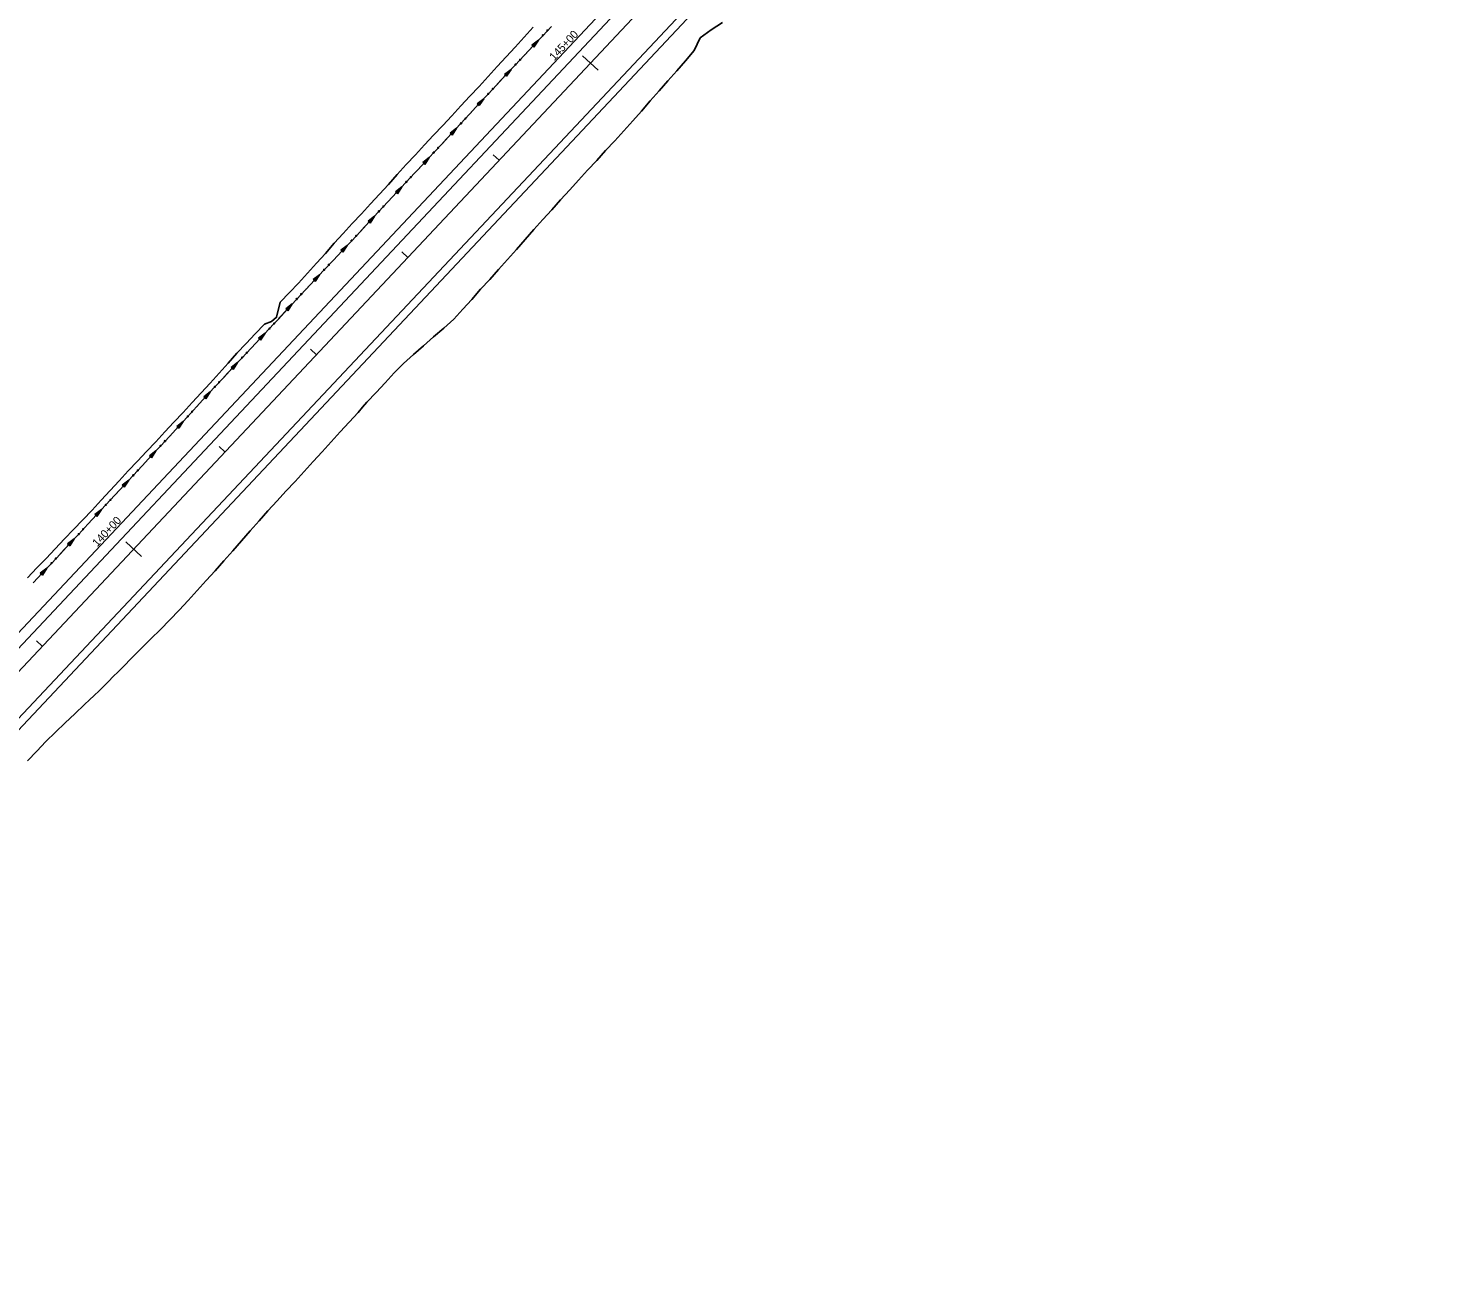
# Model space of a CAD drawing. Extents: x 1375694 to 1433473, y 1931050 to 1967991.
# Drawn here: x 1378305 to 1379358, y 1933391 to 1934333 of the extents above; entities that cross this region are included whole.
import ezdxf

# ---------------------------------------------------------------- set-up
doc = ezdxf.new("R2010")
doc.units = 0
for name, color, linetype in [('62', 7, 'Continuous'), ('R_Horz Alg', 7, 'Continuous'), ('R_Horz Alg Annot', 7, 'Continuous'), ('R_Proposed Const Limits', 7, 'Continuous'), ('R_Proposed Road', 7, 'Continuous')]:
    doc.layers.add(name, color=color, linetype=linetype)

msp = doc.modelspace()

# ---------------------------------------------------------------- linework, layer by layer
at = {"layer": '62'}
for p, q in [((1378687.5, 1934324.3), (1378682.7, 1934320.6)), ((1378682.7, 1934320.6), (1378684.2, 1934319.2)), ((1378684.2, 1934319.2), (1378687.5, 1934324.3)), ((1378667, 1934302.4), (1378662.1, 1934298.7)), ((1378662.1, 1934298.7), (1378663.7, 1934297.3)), ((1378663.7, 1934297.3), (1378667, 1934302.4)), ((1378646.5, 1934280.4), (1378641.7, 1934276.7)), ((1378641.7, 1934276.7), (1378643.2, 1934275.3)), ((1378643.2, 1934275.3), (1378646.5, 1934280.4)), ((1378626.1, 1934258.3), (1378621.3, 1934254.7)), ((1378621.3, 1934254.7), (1378622.8, 1934253.2)), ((1378622.8, 1934253.2), (1378626.1, 1934258.3)), ((1378605.6, 1934236.4), (1378600.8, 1934232.7)), ((1378600.8, 1934232.7), (1378602.3, 1934231.3)), ((1378602.3, 1934231.3), (1378605.6, 1934236.4)), ((1378585.1, 1934214.4), (1378580.3, 1934210.8)), ((1378580.3, 1934210.8), (1378581.8, 1934209.3)), ((1378581.8, 1934209.3), (1378585.1, 1934214.4)), ((1378564.6, 1934192.5), (1378559.8, 1934188.8)), ((1378561.3, 1934187.3), (1378564.6, 1934192.5)), ((1378559.8, 1934188.8), (1378561.3, 1934187.3)), ((1378544.1, 1934170.5), (1378539.3, 1934166.9)), ((1378540.8, 1934165.4), (1378544.1, 1934170.5)), ((1378539.3, 1934166.9), (1378540.8, 1934165.4)), ((1378523.5, 1934148.6), (1378518.7, 1934145)), ((1378520.2, 1934143.5), (1378523.5, 1934148.6)), ((1378518.7, 1934145), (1378520.2, 1934143.5)), ((1378503, 1934126.7), (1378498.2, 1934123)), ((1378499.7, 1934121.6), (1378503, 1934126.7)), ((1378498.2, 1934123), (1378499.7, 1934121.6)), ((1378482.6, 1934104.7), (1378477.7, 1934101)), ((1378477.7, 1934101), (1378479.3, 1934099.6)), ((1378479.3, 1934099.6), (1378482.6, 1934104.7)), ((1378462, 1934082.8), (1378457.1, 1934079.1)), ((1378457.1, 1934079.1), (1378458.7, 1934077.7)), ((1378458.7, 1934077.7), (1378462, 1934082.8)), ((1378441.5, 1934060.8), (1378436.7, 1934057.1)), ((1378436.7, 1934057.1), (1378438.3, 1934055.7)), ((1378438.3, 1934055.7), (1378441.5, 1934060.8)), ((1378421.2, 1934038.7), (1378416.4, 1934035)), ((1378416.4, 1934035), (1378417.9, 1934033.6)), ((1378417.9, 1934033.6), (1378421.2, 1934038.7)), ((1378400.8, 1934016.6), (1378396, 1934013)), ((1378396, 1934013), (1378397.5, 1934011.5)), ((1378397.5, 1934011.5), (1378400.8, 1934016.6)), ((1378380.4, 1933994.6), (1378375.6, 1933990.9)), ((1378375.6, 1933990.9), (1378377.1, 1933989.5)), ((1378377.1, 1933989.5), (1378380.4, 1933994.6)), ((1378360, 1933972.6), (1378355.1, 1933968.9)), ((1378355.1, 1933968.9), (1378356.6, 1933967.5)), ((1378356.6, 1933967.5), (1378360, 1933972.6)), ((1378339.5, 1933950.6), (1378334.6, 1933947)), ((1378334.6, 1933947), (1378336.2, 1933945.5)), ((1378336.2, 1933945.5), (1378339.5, 1933950.6)), ((1378319, 1933928.7), (1378314.1, 1933925)), ((1378315.7, 1933923.6), (1378319, 1933928.7)), ((1378314.1, 1933925), (1378315.7, 1933923.6))]:
    msp.add_line(p, q, dxfattribs=at)
for points in [[(1378308.8, 1933917.7), (1378315.6, 1933925), (1378322.4, 1933932.3), (1378329.2, 1933939.6), (1378336, 1933946.9), (1378342.9, 1933954.3), (1378349.7, 1933961.6), (1378356.5, 1933968.9), (1378363.3, 1933976.2), (1378370.1, 1933983.5), (1378376.9, 1933990.9), (1378383.7, 1933998.2), (1378390.5, 1934005.5), (1378397.3, 1934012.9), (1378404.1, 1934020.2), (1378410.9, 1934027.5), (1378417.7, 1934034.9), (1378424.5, 1934042.2), (1378431.2, 1934049.6), (1378438, 1934057), (1378444.8, 1934064.3), (1378451.6, 1934071.7), (1378458.4, 1934079), (1378465.3, 1934086.2), (1378472.1, 1934093.5), (1378479, 1934100.8), (1378485.8, 1934108.1), (1378489.2, 1934111.8), (1378492.6, 1934115.4), (1378499.4, 1934122.8), (1378506.2, 1934130.1), (1378513, 1934137.4), (1378519.9, 1934144.7), (1378526.7, 1934152), (1378533.6, 1934159.3), (1378540.4, 1934166.6), (1378547.3, 1934173.8), (1378554.1, 1934181.1), (1378560.9, 1934188.5), (1378567.7, 1934195.8), (1378574.6, 1934203.1), (1378581.4, 1934210.4), (1378588.2, 1934217.7), (1378595, 1934225), (1378601.9, 1934232.3), (1378608.7, 1934239.6), (1378615.5, 1934246.9), (1378622.3, 1934254.3), (1378629.1, 1934261.6), (1378635.9, 1934268.9), (1378642.7, 1934276.3), (1378649.5, 1934283.6), (1378656.3, 1934291), (1378663.1, 1934298.3), (1378670, 1934305.6), (1378676.8, 1934312.9), (1378683.6, 1934320.1), (1378690.5, 1934327.4), (1378697.3, 1934334.7)], [(1378677.3, 1934313.3), (1378683.6, 1934320.1), (1378687.5, 1934324.3)], [(1378677.2, 1934313.3), (1378677.3, 1934313.3)], [(1378656.7, 1934291.4), (1378663.1, 1934298.3), (1378667, 1934302.4)], [(1378656.7, 1934291.4), (1378656.7, 1934291.4)], [(1378636.3, 1934269.4), (1378642.7, 1934276.3), (1378646.5, 1934280.4)], [(1378636.3, 1934269.4), (1378636.3, 1934269.4)], [(1378615.9, 1934247.4), (1378622.3, 1934254.3), (1378626.1, 1934258.3)], [(1378615.9, 1934247.3), (1378615.9, 1934247.4)], [(1378595.4, 1934225.4), (1378601.9, 1934232.3), (1378605.6, 1934236.4)], [(1378595.4, 1934225.4), (1378595.4, 1934225.4)], [(1378574.9, 1934203.5), (1378581.4, 1934210.4), (1378585.1, 1934214.4)], [(1378574.9, 1934203.4), (1378574.9, 1934203.5)], [(1378554.4, 1934181.5), (1378560.9, 1934188.5), (1378564.6, 1934192.5)], [(1378554.4, 1934181.4), (1378554.4, 1934181.5)], [(1378533.9, 1934159.6), (1378540.4, 1934166.6), (1378544.1, 1934170.5)], [(1378533.8, 1934159.6), (1378533.9, 1934159.6)], [(1378513.3, 1934137.7), (1378519.9, 1934144.7), (1378523.5, 1934148.6)], [(1378513.2, 1934137.7), (1378513.3, 1934137.7)], [(1378492.8, 1934115.7), (1378499.4, 1934122.8), (1378503, 1934126.7)], [(1378492.8, 1934115.7), (1378492.8, 1934115.7)], [(1378472.3, 1934093.7), (1378479, 1934100.8), (1378482.6, 1934104.7)], [(1378472.3, 1934093.7), (1378472.3, 1934093.7)], [(1378451.7, 1934071.9), (1378458.4, 1934079), (1378462, 1934082.8)], [(1378451.7, 1934071.8), (1378451.7, 1934071.9)], [(1378431.4, 1934049.8), (1378438, 1934057), (1378441.5, 1934060.8)], [(1378431.4, 1934049.7), (1378431.4, 1934049.8)], [(1378411.1, 1934027.7), (1378417.7, 1934034.9), (1378421.2, 1934038.7)], [(1378411, 1934027.6), (1378411.1, 1934027.7)], [(1378390.6, 1934005.6), (1378397.3, 1934012.9), (1378400.8, 1934016.6)], [(1378390.6, 1934005.6), (1378390.6, 1934005.6)], [(1378370.2, 1933983.6), (1378376.9, 1933990.9), (1378380.4, 1933994.6)], [(1378370.2, 1933983.6), (1378370.2, 1933983.6)], [(1378349.7, 1933961.6), (1378356.5, 1933968.9), (1378360, 1933972.6)], [(1378349.7, 1933961.6), (1378349.7, 1933961.6)], [(1378329.3, 1933939.7), (1378336, 1933946.9), (1378339.5, 1933950.6)], [(1378329.2, 1933939.6), (1378329.2, 1933939.6), (1378329.3, 1933939.7)], [(1378308.8, 1933917.7), (1378315.6, 1933925), (1378319, 1933928.7)]]:
    msp.add_lwpolyline(points, dxfattribs=at)
for centre in [(1378690.9, 1934328), (1378694.3, 1934331.6), (1378670.4, 1934306.1), (1378673.8, 1934309.7), (1378649.9, 1934284.1), (1378653.3, 1934287.8), (1378632.9, 1934265.7), (1378629.5, 1934262), (1378612.4, 1934243.7), (1378609, 1934240.1), (1378591.9, 1934221.8), (1378588.5, 1934218.1), (1378571.4, 1934199.8), (1378568, 1934196.1), (1378547.5, 1934174.2), (1378551, 1934177.8), (1378526.9, 1934152.3), (1378530.4, 1934156), (1378506.4, 1934130.4), (1378509.8, 1934134.1), (1378486, 1934108.3), (1378489.4, 1934112), (1378465.4, 1934086.5), (1378468.9, 1934090.1), (1378444.9, 1934064.5), (1378448.3, 1934068.2), (1378424.6, 1934042.4), (1378428, 1934046.1), (1378404.2, 1934020.3), (1378407.6, 1934024), (1378387.2, 1934002), (1378383.8, 1933998.3), (1378366.8, 1933980), (1378363.3, 1933976.3), (1378346.3, 1933958), (1378342.9, 1933954.3), (1378325.8, 1933936), (1378322.4, 1933932.4)]:
    msp.add_circle(centre, 0.375, dxfattribs=at)
at = {"layer": 'R_Horz Alg'}
msp.add_line((1377884.3, 1933411.6), (1379607.9, 1935244.4), dxfattribs=at)
at = {"layer": 'R_Horz Alg Annot'}
for points in [[(1378720.7, 1934312.7), (1378732.4, 1934301.8)], [(1378653.7, 1934238.5), (1378658.1, 1934234.4)], [(1378585.2, 1934165.7), (1378589.6, 1934161.5)], [(1378516.7, 1934092.8), (1378521.1, 1934088.7)], [(1378448.2, 1934020), (1378452.5, 1934015.8)], [(1378378.2, 1933948.5), (1378389.9, 1933937.5)], [(1378311.2, 1933874.3), (1378315.5, 1933870.2)]]:
    msp.add_lwpolyline(points, dxfattribs=at)
at = {"layer": 'R_Proposed Const Limits'}
for points in [[(1378817.1, 1934332), (1378825.6, 1934337.7)], [(1378304.6, 1933921.6), (1378311.5, 1933928.9), (1378318.4, 1933936.1), (1378325.3, 1933943.3), (1378332.2, 1933950.6), (1378339.1, 1933957.8), (1378346, 1933965), (1378352.9, 1933972.2), (1378359.7, 1933979.6), (1378366.5, 1933986.9), (1378373.3, 1933994.2), (1378380.1, 1934001.6), (1378386.9, 1934008.9), (1378393.8, 1934016.2), (1378400.6, 1934023.5), (1378407.4, 1934030.8), (1378414.3, 1934038.1), (1378421.1, 1934045.4), (1378427.9, 1934052.8), (1378434.7, 1934060.1), (1378441.5, 1934067.4), (1378448.3, 1934074.8), (1378454.9, 1934082.3), (1378461.5, 1934089.8), (1378468.4, 1934097.1), (1378475.3, 1934104.3), (1378482.2, 1934111.5), (1378487.4, 1934113.5), (1378491.3, 1934116.7), (1378493.9, 1934128), (1378500.8, 1934135.2), (1378507.7, 1934142.4), (1378514.5, 1934149.7), (1378521.2, 1934157.2), (1378527.9, 1934164.6), (1378534.4, 1934172.2), (1378541.2, 1934179.5), (1378548, 1934186.9), (1378554.8, 1934194.3), (1378561.6, 1934201.6), (1378568.3, 1934209), (1378575.1, 1934216.3), (1378581.7, 1934223.8), (1378588.5, 1934231.1), (1378595.4, 1934238.4), (1378602.2, 1934245.8), (1378608.9, 1934253.1), (1378615.8, 1934260.4), (1378622.6, 1934267.7), (1378629.4, 1934275.1), (1378636.2, 1934282.4), (1378643, 1934289.7), (1378649.8, 1934297.1), (1378656.5, 1934304.5), (1378663.3, 1934311.8), (1378670.1, 1934319.1), (1378676.9, 1934326.5), (1378683.6, 1934334)], [(1378304.6, 1933784.3), (1378311.5, 1933791.6), (1378318.2, 1933799), (1378325.5, 1933805.9), (1378332.8, 1933812.8), (1378340.1, 1933819.6), (1378347.3, 1933826.5), (1378350.9, 1933830), (1378354.6, 1933833.4), (1378358.2, 1933836.9), (1378361.8, 1933840.4), (1378365.3, 1933843.9), (1378368.8, 1933847.5), (1378372.4, 1933851), (1378375.9, 1933854.6), (1378382.9, 1933861.7), (1378390, 1933868.8), (1378397, 1933875.9), (1378404.1, 1933882.9), (1378411.2, 1933890), (1378418.1, 1933897.2), (1378424.9, 1933904.6), (1378431.6, 1933912), (1378438.4, 1933919.4), (1378445.1, 1933926.7), (1378451.8, 1933934.2), (1378458.4, 1933941.7), (1378464.9, 1933949.3), (1378471.5, 1933956.8), (1378478.1, 1933964.3), (1378484.7, 1933971.8), (1378491.6, 1933979.1), (1378498.3, 1933986.5), (1378505.2, 1933993.8), (1378511.9, 1934001.2), (1378518.6, 1934008.6), (1378525.3, 1934016), (1378532.1, 1934023.4), (1378538.8, 1934030.8), (1378545.6, 1934038.1), (1378552.4, 1934045.5), (1378555.7, 1934049.3), (1378559, 1934053), (1378565.9, 1934060.3), (1378572.7, 1934067.6), (1378579.3, 1934075.1), (1378586.5, 1934082.1), (1378593.9, 1934088.8), (1378601.5, 1934095.4), (1378608.9, 1934102.1), (1378616.6, 1934108.6), (1378624.2, 1934115.3), (1378630.8, 1934122.7), (1378637.7, 1934130), (1378644.1, 1934137.7), (1378651, 1934145), (1378657.7, 1934152.4), (1378664.3, 1934159.9), (1378671, 1934167.4), (1378677.6, 1934174.9), (1378684.1, 1934182.4), (1378690.8, 1934189.9), (1378697.5, 1934197.3), (1378704.2, 1934204.7), (1378711, 1934212.1), (1378717.7, 1934219.5), (1378724.4, 1934227), (1378731.2, 1934234.3), (1378737.9, 1934241.7), (1378744.7, 1934249), (1378751.5, 1934256.4), (1378758.2, 1934263.8), (1378764.8, 1934271.2), (1378771.4, 1934278.8), (1378778, 1934286.3), (1378784.6, 1934293.8), (1378791.2, 1934301.4), (1378797.7, 1934308.9), (1378804.3, 1934316.6), (1378808.8, 1934326)], [(1378808.8, 1934326), (1378817.1, 1934332)]]:
    msp.add_lwpolyline(points, dxfattribs=at)
at = {"layer": 'R_Proposed Road'}
for p, q in [((1377869.7, 1933425.3), (1379593.4, 1935258.1)), ((1377875.5, 1933419.8), (1379599.2, 1935252.6)), ((1377901.7, 1933395.1), (1379625.4, 1935228)), ((1377906.1, 1933391), (1379629.8, 1935223.9))]:
    msp.add_line(p, q, dxfattribs=at)

# ---------------------------------------------------------------- texts
at = {"layer": 'R_Horz Alg Annot'}
for s, p in [('145+00', (1378699.4, 1934308.6)), ('140+00', (1378356.8, 1933944.4))]:
    msp.add_text(s, height=6, rotation=46.7586, dxfattribs=at).set_placement(p)

doc.saveas('drawing.dxf')
